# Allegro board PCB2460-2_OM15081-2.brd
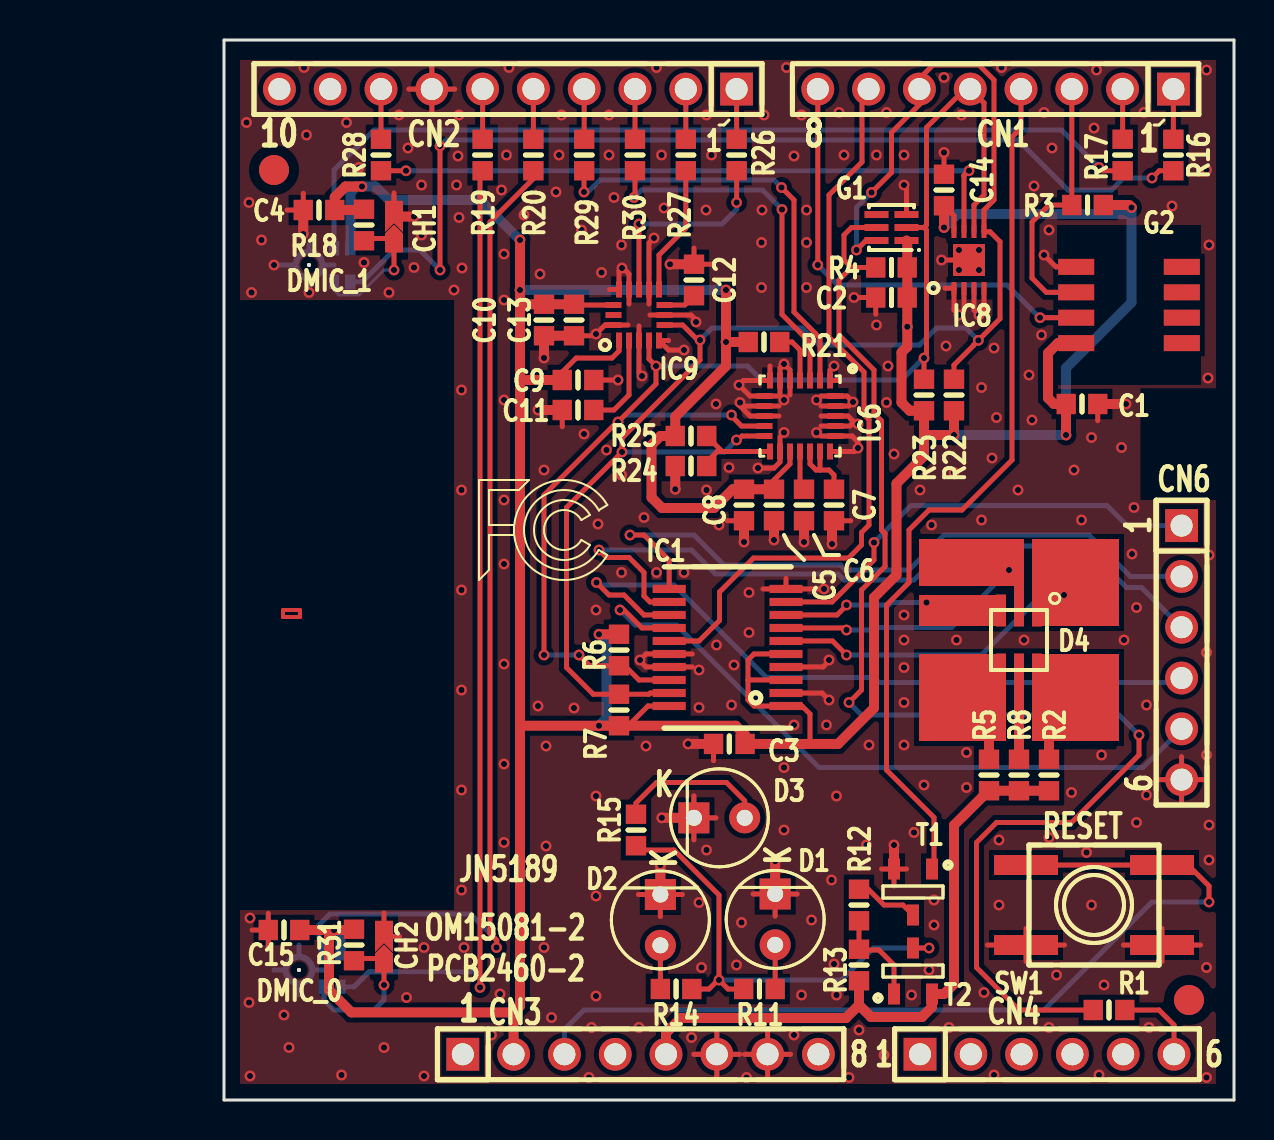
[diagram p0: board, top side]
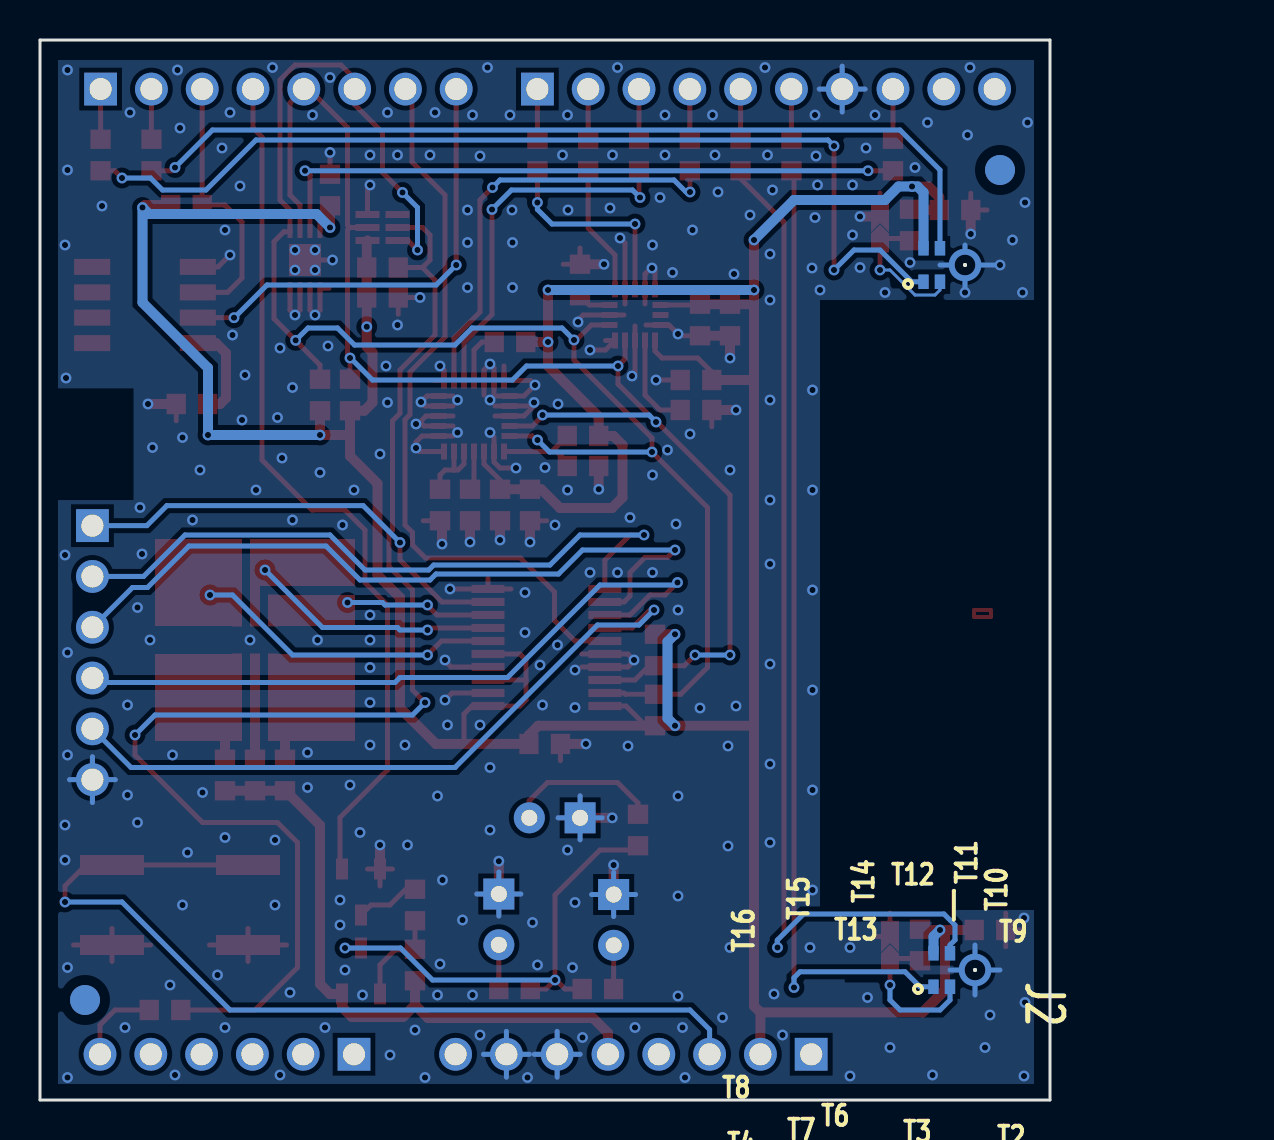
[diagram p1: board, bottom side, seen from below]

Outline 50.5 x 53 mm; copper layers: TOP, BOTTOM. Coordinates in mm from the lower left corner of the outline.
Outline path: 0,53 50.5,53 50.5,0 0,0 0,53

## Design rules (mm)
net group ALIM: nets VCC VCC3.3V VCC5V VIN
net group DEFAUT: nets I2C0_SCL I2C0_SDA N03174 N03180 N03190 N03428 N03542 N03710 N05589 N05601 N05625 N05637 N05653 N05814 N05832 N05850 N06055 N06079 N06104 N25754 N28193 N29430 N29717 N31644 N33464 N60487 N60495 N61570 N62140 N62201 N66287 N66291 N66417 N66481 N66485 N77953 N85458 PDM0_CLK PDM0_DATA PDM1_CLK PDM1_DATA PIO_2 PIO_3 PIO_4 PIO_7 PIO_15 PIO_16 PIO_18 PIO_19 PIO_21 PWM6 RSTN

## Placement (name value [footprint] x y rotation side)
1  BUBBLE-01  [BUBBLE_DIAM8]  -9.2 43.05 0 top
C1  100nF  [C0603]  42.9 34.8 0 top
C2  100nF  [C0603]  33.38 40.12 180 top
C3  100nF  [C0603]  25.27 17.8 180 top
C4  100nF  [C0603]  4.75 44.5 180 top
C5  100nF  [C0603]  27.5 29.75 270 top
C6  100nF  [C0603]  29 29.75 270 top
C7  100nF  [C0603]  30.5 29.75 90 top
C8  1uF  [C0603]  26 29.75 270 top
C9  100nF  [C0603]  17.7 36 180 top
C10  4.7uF  [C0603]  16 39 270 top
C11  100nF  [C0603]  17.7 34.5 0 top
C12  100nF  [C0603]  23.5 41 270 top
C13  100nF  [C0603]  17.5 39 90 top
C14  100nF  [C0603]  36 45.5 270 top
C15  100nF  [C0603]  3 8.5 180 top
CH1  NC  [CHEVRON_0603_O]  8.5 43.75 90 top
CH2  NC  [CHEVRON_0603_O]  8 7.75 90 top
CN1  -  [ESQ-108-14-L-S]  47.47 50.55 0 top
CN2  -  [ESQ-110-14-L-S]  25.63 50.55 0 top
CN3  -  [ESQ-108-14-L-S]  11.94 2.29 180 top
CN4  -  [ESQ-106-14-L-S]  34.8 2.29 180 top
CN6  -  [ESQ-106-14-L-S]  47.88 28.72 90 top
D1  WHITE  [LED_D5_A_K]  27.56 9.03 270 top
D2  WHITE  [LED_D5_A_K]  21.82 9 270 top
D3  WHITE  [LED_D5_A_K]  24.77 14.11 0 top
D4  B/G/R  [LED_PLCC6]  39.75 23 270 top
G1  TSL25721FN  [DFN6_065_2X2]  33.38 43.62 180 top
G2  SHT11_NC  [SENSOR_SHT11]  45.25 39.75 0 top
IC1  PCA9634  [TSSOP20_175_065]  25.18 22.63 180 top
IC4  -  [SPH0641LM4H-1]  4.25 41.75 90 bottom
IC5  -  [SPH0641LM4H-1]  3.75 6.5 90 bottom
IC6  FXAS21002C  [QFN24_050_4X4]  28.8 34.2 270 top
IC8  SE98ATP  [SOT1069-2_HWSON8]  37.25 42 0 top
IC9  FXOS8700CQR1  [QFN16_050_SQ3_NOPAD]  20.75 39.25 90 top
NOREF  -  []  315.6 -90.1 0 top
NOREF#2  -  [unnamed#2]  2.5 46.5 0 top
NOREF#3  -  []  16 0 90 top
NOREF#4  -  []  2.77 50.55 90 top
NOREF#5  -  []  13.7 -115.75 0 top
NOREF#6  -  []  -76.6 -194.1 0 top
NOREF#7  -  []  62.65 28.15 0 top
NOREF#8  -  []  0 0 90 top
NOREF#9  -  []  0 53 0 top
NOREF#10  -  []  0 53 0 top
NOREF#11  -  [unnamed#2]  48.25 5 0 top
NOREF#12  -  []  49.25 30.25 90 top
NOREF#13  -  []  299.4 3.2 0 top
NOREF#14  -  [unnamed#2]  48.25 5 180 bottom
NOREF#15  -  [unnamed#2]  2.5 46.5 180 bottom
R1  0R  [R0603]  44.25 4.5 0 top
R2  100R  [R0603]  41.25 16.25 90 top
R3  10K0  [R0603]  43.18 44.75 0 top
R4  10K0  [R0603]  33.38 41.62 180 top
R5  200R  [R0603]  38.25 16.25 90 top
R6  10K0  [R0603]  19.75 22.5 270 top
R7  10K0  [R0603]  19.75 19.5 90 top
R8  100R  [R0603]  39.75 16.25 90 top
R11  100R  [R0603]  26.77 5.55 0 top
R12  1K  [R0603]  31.75 9.75 270 top
R13  1K  [R0603]  31.75 6.75 270 top
R14  100R  [R0603]  22.61 5.55 180 top
R15  100R  [R0603]  20.6 13.5 90 top
R16  0R  [R0603]  47.47 47.25 90 top
R17  0R  [R0603]  44.93 47.25 90 top
R18  100K  [R0603]  7 43.75 270 top
R19  0R  [R0603]  12.93 47.25 90 top
R20  0R  [R0603]  15.47 47.25 90 top
R21  47K0  [R0603]  27 37.9 0 top
R22  4K70  [R0603]  36.5 35.25 90 top
R23  4K70  [R0603]  35 35.25 90 top
R24  NC  [R0603]  23.35 31.7 180 top
R25  47K0  [R0603]  23.35 33.2 180 top
R26  0R  [R0603]  25.63 47.25 90 top
R27  0R  [R0603]  23.09 47.25 90 top
R28  0R  [R0603]  7.85 47.25 90 top
R29  0R  [R0603]  18.01 47.25 270 top
R30  0R  [R0603]  20.55 47.25 270 top
R31  100K  [R0603]  6.5 7.75 270 top
SW1  EVQ-Q2P03W  [BP_EVQQ2]  43.5 9.75 0 top
T1  MMUN2211LT1G  [SOT23]  34.45 10.4 180 top
T2  BCV26  [SOT23]  34.45 6.45 0 top

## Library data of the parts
1 = BUBBLE: alternate symbols: (BUBBLE_DIAM4)
C1-C15 = CAPA: Tolerance: 10%; User Part Number: PARTNUM; alternate symbols: (0603C); tolerance: 10%
CH1 CH2 = CHEVRON_0603_OPEN
CN1 CN3 = HEADER_8P: Tolerance: TOL; User Part Number: PAR
CN2 = HEADER_10P: Tolerance: TOL; User Part Number: PAR
CN4 CN6 = HEADER_6P: Tolerance: TOL; User Part Number: PAR
D1-D3 = LED: User Part Number: PAR; Tolerance: TOL
D4 = LED_3_PLCC6: Tolerance: t; User Part Number: p
G1 = sensor_tsl2572_fn-6
G2 = SENSOR_SHT11: User Part Number: PARTNUM; Tolerance: TOLERANCE
IC1 = PCA9634_TSSOP20
IC4 IC5 = SPH0641LM4H-1: User Part Number: PARTNUM; Tolerance: TOLERANCE
IC6 = FXAS21002C
IC8 = SE98ATP: Tolerance: TOL; User Part Number: PN
IC9 = FXOS8700CQR1: User Part Number: BCNNUMBER; Tolerance: TOLERANCE
R1 R2 R5 R8 R11-R20 R26-R31 = RES: User Part Number: PARTNUM; Tolerance: 1%; alternate symbols: (0603R); tolerance: 1%
R3 R4 R6 R7 = RES: User Part Number: PARTNUM; Tolerance: 1%; tolerance: 1%
R21-R23 R25 = RES: User Part Number: PARTNUM; Tolerance: 5%; tolerance: 5%
R24 = RES: User Part Number: PARTNUM; Tolerance: -; tolerance: -
SW1 = BP_EVQQ2: User Part Number: PARTNUM; Tolerance: TOLERANCE
T1 = NPN_B1_E2_C3: User Part Number: PARTNUM; Tolerance: TOLERANCE
T2 = PNP_B1_E2_C3: User Part Number: PARTNUM; Tolerance: TOLERANCE

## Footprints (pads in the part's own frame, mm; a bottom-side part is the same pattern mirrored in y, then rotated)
BP_EVQQ2
  rect 3.2x1 smd: A(-3.4,-2) AP(3.4,-2) B(-3.4,2) BP(3.4,2)
BUBBLE_DIAM8
  round 0 smd: 1(0,0)
C0603
  rect 0.965x1.016 smd: 1(-0.787,0) 2(0.787,0)
CHEVRON_0603_O
  custom 0.225x0.225 smd: 1(-0.675,0) 2(0.425,0)
DFN6_065_2X2
  rect 1.2x0.35 smd: 1(-0.75,0.65) 2(-0.75,0) 3(-0.75,-0.65) 4(0.75,-0.65) 5(0.75,0) 6(0.75,0.65)
ESQ-106-14-L-S
  rect 1.64x1.64 hole 1.1: 1(0,0)
  round 1.64 hole 1.1: 2(-2.54,0) 3(-5.08,0) 4(-7.62,0) 5(-10.16,0) 6(-12.7,0)
ESQ-108-14-L-S
  rect 1.64x1.64 hole 1.1: 1(0,0)
  round 1.64 hole 1.1: 2(-2.54,0) 3(-5.08,0) 4(-7.62,0) 5(-10.16,0) 6(-12.7,0) 7(-15.24,0) 8(-17.78,0)
ESQ-110-14-L-S
  rect 1.64x1.64 hole 1.1: 1(0,0)
  round 1.64 hole 1.1: 2(-2.54,0) 3(-5.08,0) 4(-7.62,0) 5(-10.16,0) 6(-12.7,0) 7(-15.24,0) 8(-17.78,0) 9(-20.32,0) 10(-22.86,0)
LED_D5_A_K
  round 1.55 hole 0.8: A(1.27,0)
  rect 1.55x1.55 hole 0.8: K(-1.27,0)
LED_PLCC6
  rect 1.6x0.5 smd: 1(-1.475,0.9) 2(-1.475,0) 3(-1.475,-0.9) 4(1.475,-0.9) 5(1.475,0) 6(1.475,0.9)
QFN16_050_SQ3_NOPAD
  rect 0.8x0.3 smd: 1(-1.275,1) 2(-1.275,0.5) 3(-1.275,0) 4(-1.275,-0.5) 5(-1.275,-1) 9(1.275,-1) 10(1.275,-0.5) 11(1.275,0) 12(1.275,0.5) 13(1.275,1)
  rect 0.3x0.8 smd: 6(-0.5,-1.275) 7(0,-1.275) 8(0.5,-1.275) 14(0.5,1.275) 15(0,1.275) 16(-0.5,1.275)
QFN24_050_4X4
  rect 0.8x0.3 smd: 1(-1.775,1.5) 2(-1.775,1) 3(-1.775,0.5) 4(-1.775,0) 5(-1.775,-0.5) 6(-1.775,-1) 7(-1.775,-1.5) 13(1.775,-1.5) 14(1.775,-1) 15(1.775,-0.5) 16(1.775,0) 17(1.775,0.5) 18(1.775,1) 19(1.775,1.5)
  rect 0.3x0.8 smd: 8(-1,-1.775) 9(-0.5,-1.775) 10(0,-1.775) 11(0.5,-1.775) 12(1,-1.775) 20(1,1.775) 21(0.5,1.775) 22(0,1.775) 23(-0.5,1.775) 24(-1,1.775)
R0603
  rect 0.965x1.016 smd: 1(-0.787,0) 2(0.787,0)
SENSOR_SHT11
  rect 1.8x0.8 smd: 1(-2.64,1.905) 2(-2.64,0.635) 3(-2.64,-0.635) 4(-2.64,-1.905) 5(2.64,-1.905) 6(2.64,-0.635) 7(2.64,0.635) 8(2.64,1.905)
SOT23
  rect 0.6x1.05 smd: 1(-0.95,-1.15) 2(0.95,-1.15) 3(0,1.15)
SOT1069-2_HWSON8
  rect 0.25x0.625 smd: 1(-0.75,-1.413) 2(-0.25,-1.413) 3(0.25,-1.413) 4(0.75,-1.413) 5(0.75,1.413) 6(0.25,1.413) 7(-0.25,1.413) 8(-0.75,1.413)
  rect 1.6x1.6 smd: 9(0,0)
SPH0641LM4H-1
  round 0.2 hole 0.35 unplated: (0,0)
  rect 0.725x0.522 smd: 1(-0.838,2.074) 2(-0.838,1.252) 4(0.838,1.252) 5(0.838,2.074)
  round 0.25 smd: 3(0,-0.675)
TSSOP20_175_065
  rect 1.651x0.406 smd: 1(-2.921,2.926) 2(-2.921,2.276) 3(-2.921,1.626) 4(-2.921,0.975) 5(-2.921,0.325) 6(-2.921,-0.325) 7(-2.921,-0.975) 8(-2.921,-1.626) 9(-2.921,-2.276) 10(-2.921,-2.926) 11(2.921,-2.926) 12(2.921,-2.276) 13(2.921,-1.626) 14(2.921,-0.975) 15(2.921,-0.325) 16(2.921,0.325) 17(2.921,0.975) 18(2.921,1.626) 19(2.921,2.276) 20(2.921,2.926)
unnamed#2
  round 1.5 smd: (0,0)

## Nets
GND: C1.2 C2.2 C3.2 C4.2 C5.2 C6.2 C7.1 C8.2 C9.1 C10.2 C11.1 C12.1 C13.1 C14.1 C15.2 CH1.2 CH2.2 CN2.7 CN3.6 CN3.7 CN6.6 D1.K D2.K D3.K G1.3(GND) G2.1(GND) IC1.2(A1) IC1.4(A3) IC1.10(GND) IC1.16(A5) IC1.17(A6) IC4.3(GND) IC5.3(GND) IC6.1(GND1) IC6.5(GND2) IC6.6(RSVD) IC6.7(RSVD2) IC6.8(I2C/SPI) IC6.9(RSVD/GND) IC6.10(RSVD/GND2) IC6.14(GND3) IC6.19(GND4) IC6.20(RSVD3) IC6.21(RSVD4) IC6.22(RSVD5) IC6.23(RSVD6) IC6.24(RSVD7) IC8.1(A0) IC8.2(A1) IC8.3(A2) IC8.4(VSS) IC8.9(PAD) IC9.3(RESERVED) IC9.5(GND) IC9.7(SA0/MISO) IC9.10(SA1/CS_B) IC9.12(GND2) IC9.13(RESERVED2) IC9.16(RST) R24.2 SW1.A SW1.AP T1.2(E)
VCC: C1.1 C2.1 C3.1 C4.1 C5.1 C8.1 C9.2 C10.1 C13.2 C14.2 C15.1 CN3.2 G1.1(VDD) G2.4(VDD) IC1.1(AO) IC1.3(A2) IC1.5(A4) IC1.20(VCC) IC4.5(VDD) IC5.5(VDD) IC6.15(VDD) IC8.8(VDD) IC9.1(VDDIO) IC9.14(VDD) R3.2 R4.1 R6.1 R7.1 R18.1 R21.1 R22.1 R23.1 R25.2 R31.1
VCC3.3V: CN3.4
VCC5V: CN3.5 R2.1 R5.1 R8.1 R13.2 T2.2(E)
VIN: CN3.8
I2C0_SCL: CN1.5 G1.2(SCL) IC1.18(SCL) IC6.11(SCL/SCLK) IC8.6(SCL) IC9.4(SCL/SCLK) R6.2 R23.2
I2C0_SDA: CN1.6 G1.6(SDA) IC1.19(SDA) IC6.12(SDA/MOSI) IC8.5(SDA) IC9.6(SDA/MOSI) R7.2 R22.2
PDM0_CLK: CN2.5 R20.2
PDM0_DATA: CN2.6 R19.2
PDM1_CLK: CN1.2 R17.2
PDM1_DATA: CN1.1 R16.2
PIO_2: CN2.4 R29.1
PIO_3: CN2.2 R27.2
PIO_4: CN2.3 R30.1
PIO_7: CN1.8 G2.3(SCK)
PIO_15: CN1.3 G2.2(DATA) R3.1
PIO_16: CN1.7 IC1.15(OE)
PIO_18: CN2.1 R26.2
PIO_19: CN2.8 R28.2
PIO_21: CN4.6 R1.2
PWM6: CN1.4 T1.1(B)
RSTN: CN3.3 SW1.B SW1.BP
N03174: D1.A R11.2
N03180: D2.A R14.2
N03190: D3.A R15.2
N03428: R11.1 R14.1 R15.1 T2.3(C)
N03542: R12.2 R13.1 T2.1(B)
N03710: R12.1 T1.3(C)
N05589: CN6.5 IC1.14(L7)
N05601: CN6.4 IC1.13(L6)
N05625: CN6.3 IC1.12(L5)
N05637: CN6.2 IC1.11(L4)
N05653: CN6.1 IC1.9(L3)
N05814: D4.3(K3) IC1.8(L2)
N05832: D4.2(K2) IC1.7(L1)
N05850: D4.1(K1) IC1.6(L0)
N06055: D4.6(A6) R2.2
N06079: D4.5(A5) R8.2
N06104: D4.4(A4) R5.2
N25754: IC6.4(RST_B) R21.2
N28193: IC6.13(SA0/MISO) R24.1 R25.1
N29430: C6.1 IC6.16(VREGD)
N29717: C7.2 IC6.17(SPI_CS_B) IC6.18(VDDIO)
N31644: C11.2 IC9.2(BYP)
N33464: C12.2 IC9.8(CRST)
N60487: IC9.11(INT1) R26.1
N60495: IC9.9(INT2) R27.1
N61570: IC8.7(EVENT) R28.1
N62140: IC6.2(INT2) R29.2
N62201: IC6.3(INT1) R30.2
N66287: IC4.1(DATA) R16.1
N66291: IC4.4(CLK) R17.1
N66417: CH1.1 IC4.2(SELECT) R18.2
N66481: IC5.1(DATA) R19.1
N66485: IC5.4(CLK) R20.1
N77953: CH2.1 IC5.2(SELECT) R31.2
N85458: G1.5(INT) R1.1 R4.2

Pads without a net: 1 1; CN2 9 10; CN3 1; CN4 1 2 3 4 5; G1 4; G2 5 6 7 8; IC9 15

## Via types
v1: diameter 0.54, hole 0.31, TOP to BOTTOM, 331 vias

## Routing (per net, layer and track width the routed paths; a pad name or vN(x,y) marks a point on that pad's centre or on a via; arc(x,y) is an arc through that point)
GND: length 184.4
  TOP w0.25: v1(30.5,36.7) 30.3,36.5 IC6.1 30.78,35.98 ; v1(30.25,22) 30.25,21.95 29.95,21.65 IC1.4 ; 9.24,50.55 CN2.7 ; CN2.7 10.39,49.4 ; CN2.7 11.54,50.55 ; CN2.7 10.39,51.69 ; SW1.A 40.1,8.58 ; SW1.A 38.17,7.75 ; SW1.A 40.1,6.92 ; SW1.A 42.03,7.75 ; 27.3,36.7 IC6.7 25.98,35.98 v1(25.75,35.75) 26.3,35.2 27.75,35.2 ; CN3.7 27.18,3.43 ; CN3.7 28.33,2.29 ; CN3.7 27.18,1.14 ; CN3.7 26.03,2.29 ; 46.9,6.92 SW1.AP ; SW1.AP 48.83,7.75 ; SW1.AP 44.97,7.75 ; SW1.AP 46.9,8.58 ; 20.2,38.75 IC9.16 19.05,38.75 v1(18.6,38.3) ; 33.5,10.7 T1.2 ; T1.2 34.13,11.55 ; T1.2 32.87,11.55 ; 24.64,1.14 CN3.6 ; CN3.6 24.64,3.43 ; CN3.6 25.79,2.29 ; CN3.6 23.49,2.29 ; 24.33,41.79 C12.1 23.5,42.6 ; 30.3,32.42 31.52,32.42 v1(31.7,32.6) 31.7,32.9 31.4,33.2 IC6.20 29.85,33.2 ; CN6.6 47.88,17.16 ; CN6.6 46.73,16.02 ; CN6.6 47.88,14.87 ; CN6.6 49.02,16.02 ; IC8.2 37,39.5 v1(36.75,39.25) 36.5,39.5 IC8.1 36.05,40.59 ; 21.25,39.8 IC9.10 21.25,42.85 v1(21.5,43.1) ; 23.41,21.65 IC1.17 21.1,21.65 20.8,21.95 v1(20.8,22) 21.1,22.3 IC1.16 23.41,22.3 ; 25.17,28.96 C8.2 ; 24.48,16.97 C3.2 ; 2.21,7.67 C15.2 ; C15.2 1.4,8.5 ; C15.2 2.21,9.33 ; G2.1 41.59,41.66 v1(41,42.25) ; 29.85,33.7 IC6.21 31.3,33.7 31.4,33.8 31.6,33.8 ; 27.56,9.2 D1.K ; D1.K 26.46,10.3 ; D1.K 28.66,10.3 ; D3.K 24.6,14.11 ; D3.K 23.5,15.21 ; D3.K 23.5,13.01 ; v1(34,45.75) 34.12,45.62 G1.3 ; IC1.2 29.9,20.35 v1(30.25,20) ; 28.3,35.25 IC6.5 28.3,36.5 v1(28,36.8) 27.8,36.6 IC6.6 27.8,35.25 ; 21.82,9.17 D2.K ; D2.K 20.72,10.27 ; D2.K 22.92,10.27 ; C13.1 18.33,38.21 ; 27.75,34.2 26.3,34.2 25.8,34.7 ; IC8.3 37.5,39.5 v1(37.75,39.25) 38,39.5 IC8.4 ; 30.5,28.15 C7.1 31.33,28.96 ; IC1.10 28.1,26.08 ; IC1.10 v1(30,25.55) ; IC1.10 26.95,25.55 ; 16.91,33.67 C11.1 ; 32.59,39.29 C2.2 31.78,40.12 ; 21.3,39.25 IC9.7 23.35,39.25 23.6,39 v1(23.6,38.9) ; 29.85,34.7 IC6.23 31.25,34.7 v1(31.45,34.9) 31.15,35.2 IC6.24 29.85,35.2 ; 25.8,34.7 v1(25.8,34.88) ; 25.8,34.7 27.75,34.7 ; 8,9.35 CH2.2 8.78,8.18 ; 3.15,44.5 C4.2 3.96,45.33 ; 29.85,34.2 IC6.22 31.2,34.2 31.6,33.8 ; 27.8,33.15 27.8,31.9 27.5,31.6 v1(26.7,31.6) ; 22.23,37.98 IC9.5 22.23,37.5 v1(23,37.5) ; 31.6,33.8 v1(31.7,33.8) ; C9.1 v1(19.7,36) ; C14.1 v1(36,47.38) ; CH1.2 8.5,45.35 ; 36.12,42 IC8.9 ; 20.75,38.7 IC9.3 20.75,36.35 v1(20.9,36.2) ; 43.69,33.97 C1.2 ; 20.25,39.8 IC9.12 20.25,41.3 19.95,41.6 v1(19.9,41.6) 19.75,41.45 IC9.13 19.27,40.52
  TOP w0.5: CH1.2 v1(9.5,44.17) ; T1.2 v1(33.5,12.75) ; C8.2 v1(26,27.9) ; C13.1 C10.2 v1(16,37.1) ; D2.K v1(21.82,11.75) ; C6.2 v1(29,27.9) ; C3.2 v1(23.2,17.8) ; D3.K v1(21.89,14.11) ; C5.2 v1(27.5,28) ; C12.1 v1(22.3,41.79) ; C1.2 v1(45.1,34.8) ; D1.K v1(27.56,11.94) ; C11.1 v1(15.7,34.5) ; R24.2 v1(22.56,30.54) ; C7.1 30.4,28.86 v1(30.4,27.8) ; v1(3.96,43.3) C4.2
  BOTTOM w0.25: 26.46,10.3 D1.K ; D1.K 28.66,10.3 ; D1.K 27.56,9.2 ; D1.K 27.56,11.4 ; 4.25,41 v1(4.25,40.38) ; CN3.7 28.33,2.29 ; CN3.7 26.03,2.29 ; CN3.7 27.18,1.14 ; CN3.7 27.18,3.43 ; 4.25,42.5 4.25,42.75 ; 10.39,49.4 CN2.7 ; CN2.7 10.39,51.69 ; CN2.7 9.24,50.55 ; CN2.7 11.54,50.55 ; CN6.6 47.88,17.16 ; CN6.6 46.73,16.02 ; CN6.6 49.02,16.02 ; CN6.6 47.88,14.87 ; D3.K 23.5,15.21 ; D3.K 23.5,13.01 ; D3.K 22.39,14.11 ; D3.K 24.6,14.11 ; IC5.3 2.5,6.5 ; 23.49,2.29 CN3.6 ; CN3.6 25.79,2.29 ; CN3.6 24.64,1.14 ; CN3.6 24.64,3.43 ; 20.72,10.27 D2.K ; D2.K 21.82,9.17 ; D2.K 21.82,11.37 ; D2.K 22.92,10.27 ; IC4.3 v1(2.5,41.75) ; 5.5,41.75 5,41.75 ; 5,6.5 4.5,6.5 ; 3.75,5.25 3.75,5.75 ; 3.75,7.75 3.75,7.25
  vias: v1(1.12,48.88) v1(1.25,44.88) v1(1.25,4.88) v1(1.3,9.1) v1(1.3,1.2) v1(1.38,40.38) v1(1.88,43) v1(3,4.25) v1(3.25,2.62) v1(4,51.62) v1(4.12,48.25) v1(5.88,1.25) v1(6.12,48.88) v1(6.75,46.62) v1(7,41.88) v1(8,2.62) v1(8.25,40.38) v1(8.75,49.25) v1(9.12,5.12) v1(9.2,47.6) v1(9.5,41.62) v1(9.88,45.75) v1(9.88,43.25) v1(10,7.62) v1(10,1.2) v1(11.5,40.5) v1(11.62,45.75) v1(11.7,47.2) v1(11.75,49.25) v1(11.75,44.12) v1(11.9,41.6) v1(11.88,35.5) v1(11.88,30.5) v1(11.88,25.5) v1(11.88,20.5) v1(11.88,15.5) v1(11.88,10.5) v1(12,7.62) v1(13.38,3.25) v1(13.8,5.3) v1(13.88,45.5) v1(14,42.3) v1(14,40) v1(14,35) v1(14,30) v1(14,26.8) v1(14,21.8) v1(14,16.8) v1(14,12.88) v1(14.12,47.25) v1(14.25,51.62) v1(15,44.25) v1(15.7,19.7) v1(15.8,41.3) v1(16,31.5) v1(16,7.62) v1(16.1,17.7) v1(16.1,12.7) v1(16.38,4.12) v1(16.6,45.4) v1(16.75,47.25) v1(16.88,49.25) v1(17.5,19.6) v1(17.88,43.5) v1(18,33.3) v1(18.25,1.12) v1(18.38,3.62) v1(18.6,24.5) v1(18.6,15.2) v1(18.6,10.2) v1(18.6,5.2) v1(18.7,28.8) v1(18.88,41.38) v1(19.12,32.5) v1(19.25,49.25) v1(19.25,47.25) v1(19.5,45.12) v1(19.88,42.75) v1(19.88,31.25) v1(19.88,26.38) v1(20.75,3.62) v1(21,29.12) v1(21.1,17.7) v1(21.62,51.62) v1(21.62,26.38) v1(21.88,47.25) v1(22,44.6) v1(23,26.38) v1(23.38,3.12) v1(23.75,21.5) v1(23.75,19.62) v1(23.75,9.88) v1(23.88,6.62) v1(24.12,49.25) v1(24.1,44.5) v1(24.12,30.5) v1(24.12,12.5) v1(24.38,47.25) v1(24.6,34.8) v1(24.62,22.75) v1(24.75,28.75) v1(25.25,31.62) v1(25.38,19.75) v1(25.5,21.75) v1(25.62,6.75) v1(25.88,8.88) v1(26.12,1.12) v1(26.25,25.38) v1(26.25,23.38) v1(26.9,44.5) v1(26.88,42.88) v1(26.88,40.62) v1(27,49.25) v1(28,35) v1(28,33.38) v1(28,16.62) v1(28,13.5) v1(28.12,51.62) v1(28.5,47.2) v1(28.5,18.75) v1(28.5,3.25) v1(28.88,49.25) v1(28.88,5.25) v1(29.12,44.5) v1(29.12,42.88) v1(29.12,40.62) v1(29.38,9) v1(29.62,35) v1(29.62,33.38) v1(30.12,18.75) v1(30.38,11) v1(30.5,6.8) v1(30.62,15.2) v1(30.62,5.25) v1(30.75,49.38) v1(31,47.25) v1(31.25,1.12) v1(31.5,40.12) v1(31.75,3.5) v1(32.12,12.75) v1(32.25,17.75) v1(32.62,47.25) v1(32.62,38.75) v1(33,2.25) v1(33.12,49.38) v1(33.12,34.88) v1(33.2,36.7) v1(33.5,32.3) v1(34,47.25) v1(34,24.25) v1(34,23) v1(34,21.62) v1(34,19.88) v1(34,17.75) v1(34.38,5.25) v1(34.5,13.38) v1(34.8,30.5) v1(35,15.75) v1(35.25,6.5) v1(35.38,28.75) v1(35.5,10) v1(35.5,8.75) v1(35.88,42) v1(36,51.12) v1(36.1,37.7) v1(36.25,3.62) v1(36.5,31.38) v1(36.62,23) v1(36.75,42.5) v1(36.75,41.5) v1(36.88,49.25) v1(37.12,17.38) v1(37.12,15.62) v1(37.75,42.5) v1(37.75,41.5) v1(37.88,35.62) v1(37.88,29) v1(38,5.38) v1(38.4,32.1) v1(38.5,37.6) v1(38.5,1.25) v1(38.62,34.12) v1(38.75,13) v1(38.75,9.75) v1(38.88,51.62) v1(39.7,30.5) v1(40,23) v1(40.25,36.25) v1(40.4,34) v1(40.5,45.7) v1(40.88,38.25) v1(41,49.38) v1(41.25,43.5) v1(41.25,13.12) v1(41.25,3.62) v1(41.4,47.6) v1(41.62,6.25) v1(42.38,15.38) v1(42.5,31.5) v1(42.88,29) v1(43.12,12.38) v1(43.38,33.12) v1(43.38,9.75) v1(43.5,48.6) v1(43.62,51.5) v1(43.75,1.25) v1(43.88,17.25) v1(44,5.75) v1(44.88,32.62) v1(45,23) v1(45.4,27.3) v1(45.5,29.62) v1(45.62,24.62) v1(45.62,13.88) v1(46,49.38) v1(46.12,19.75) v1(46.12,15.25) v1(46.25,3.62) v1(47.4,44.7) v1(49.12,51.5) v1(49.12,46.5) v1(49.12,22.38) v1(49.12,17.25) v1(49.12,6.62) v1(49.12,1.12) v1(49.25,42.75) v1(49.2,36.1) v1(49.25,27.25) v1(49.25,13.75) v1(49.25,12)
VCC: length 222.7
  TOP w0.25: IC1.5 26.5,22.3 26.2,22 26.2,21 ; 28.3,32.42 28.3,31.8 27.5,31 C5.1 ; IC9.14 17.54,39.75 C13.2 ; IC9.1 19.75,37.45 19.4,37.1 17.61,37.1 16.91,36.4 C9.2 ; C14.2 36.5,44.21 IC8.8 ; 26.2,21 IC1.3 ; 26.2,21 26.2,20 26.5,19.7 IC1.1 28.9,19.7 29.3,19.3 29.3,17.9 29.2,17.8 ; IC1.20 21.2,19.7 20.21,18.71
  TOP w0.5: 14.48,4.38 14.8,4.7 14.8,18.75 ; 14.48,4.38 CN3.2 ; 14.48,4.38 6.37,4.38 5.25,5.5 5.25,8.25 v1(5.5,8.5) ; v1(6.9,45.68) 6.08,45.68 5.54,45.14 C4.1 6.96,44.5 R18.1 ; 14.8,18.75 14.84,18.71 v1(18.75,18.71) R7.1 25.59,18.71 26.05,18.25 C3.1 30.7,17.8 32.5,19.6 32.5,25.12 33.62,26.25 33.62,30.82 35,32.2 35,33.2 ; 14.8,18.75 14.8,36 ; 14.8,36 14.8,39.79 ; 14.8,36 C9.2 ; v1(45.38,44.62) 45.25,44.75 R3.2 ; R31.1 6.46,8.5 v1(5.5,8.5) ; R6.1 v1(18.75,23.29) ; 14.8,39.79 v1(14.8,40.5) v1(14.8,43) ; 14.8,39.79 C10.1 C13.2 ; 35,33.2 R23.1 34.29,34.46 33.88,34.88 33.88,37.38 34.16,37.66 v1(34.16,38.66) C2.1 R4.1 34.16,42.94 G1.1 ; 35,33.2 35.05,33.25 v1(36.5,33.25) R22.1 ; v1(42.1,33.25) 42.1,34.79 C1.1 41.5,34.8 41.2,35.1 41.2,37.34 41.7,37.84 G2.4 ; C5.1 C8.1 25.44,30.54 24.5,29.6 21.9,29.6 21.38,30.12 21.38,32.75 21.82,33.2 R25.2 22.56,34.16 25.1,36.7 v1(25.1,37.9) ; v1(5.5,8.5) C15.1 ; v1(25.1,37.9) R21.1 ; v1(25.1,37.9) v1(25.1,40.5) ; C14.2 v1(36,43.62)
  BOTTOM w0.5: v1(18.75,18.71) 19.12,19.09 19.12,22.91 v1(18.75,23.29) ; v1(36,43.62) 36.67,44.3 45.05,44.3 v1(45.38,44.62) 45.38,39.88 42.1,36.6 v1(42.1,33.25) v1(36.5,33.25) ; v1(14.8,43) 12.8,45 8.25,45 7.57,45.68 v1(6.9,45.68) 6.62,45.68 6.32,45.38 IC4.5 ; IC5.5 5.82,8.18 v1(5.5,8.5) ; v1(25.1,40.5) v1(14.8,40.5)
VCC5V: length 32
  TOP w0.5: R2.1 R8.1 R5.1 38.22,15.46 36.5,13.74 36.5,5.8 36,5.3 T2.2 35.4,4.65 34.9,4.15 32.35,4.15 31.75,4.75 ; 31.75,4.75 31.1,4.1 22.85,4.1 22.1,3.35 CN3.5 ; 31.75,4.75 R13.2
I2C0_SCL: length 71.1
  TOP w0.25: IC8.6 37.5,44.75 38,45.25 38,49.86 CN1.5 37.05,50.55 35.12,48.62 35.12,43.75 35,43.62 ; v1(16,22.25) 16,30.25 19.65,33.9 v1(19.7,33.9) 21.6,35.8 v1(21.6,36.7) 21.25,37.05 IC9.4 ; IC1.18 20.75,21 20.04,21.71 R6.2 18.29,21.71 v1(17.75,22.25) ; 35,43.62 35.12,43.5 35.12,37.23 v1(35,37.1) R23.2 ; 35,43.62 G1.2 ; 27.02,33.7 25.88,33.7 25.38,34.2 v1(25.38,34.25)
  BOTTOM w0.25: v1(19.7,33.9) 20.05,34.25 v1(25.38,34.25) ; v1(17.75,22.25) v1(16,22.25) ; v1(35,37.1) 34.98,37.1 33.88,36 26.88,36 26.18,36.7 v1(21.6,36.7)
I2C0_SDA: length 81.5
  TOP w0.25: G1.6 32.1,42.98 v1(31.62,42.5) ; IC1.19 21.31,20.35 21.25,20.29 R7.2 18.46,20.29 17.12,21.62 17.12,29.62 v1(19.9,32.4) 19.9,33.1 23.8,37 v1(23.8,38) 23.68,38 22.93,38.75 IC9.6 ; v1(32.38,45.38) 33.38,46.38 33.38,48.38 34.77,49.77 CN1.6 34.77,51.07 35.45,51.75 37.75,51.75 38.5,51 38.5,45 38,44.5 IC8.5 38.3,43.41 38.8,42.91 38.8,39.07 v1(37.72,37.98) 37.48,37.75 37.48,37.73 36.5,36.75 R22.2 ; 27.02,33.2 25.9,33.2 25.7,33 v1(25.62,33)
  BOTTOM w0.25: v1(25.62,33) 25.02,32.4 v1(19.9,32.4) ; v1(32.38,45.38) 31.62,44.62 v1(31.62,42.5) ; v1(37.72,37.98) 37.1,38.6 35.62,38.6 34.77,37.75 29.75,37.75 28.9,38.6 24.4,38.6 v1(23.8,38)
PDM0_CLK: length 2.5
  TOP w0.25: CN2.5 R20.2
PDM0_DATA: length 2.5
  TOP w0.25: CN2.6 R19.2
PDM1_CLK: length 2.5
  TOP w0.25: CN1.2 R17.2
PDM1_DATA: length 2.5
  TOP w0.25: CN1.1 R16.2
PIO_2: length 2.5
  TOP w0.25: CN2.4 R29.1
PIO_3: length 2.5
  TOP w0.25: CN2.2 R27.2
PIO_4: length 2.5
  TOP w0.25: CN2.3 R30.1
PIO_7: length 22.8
  TOP w0.25: v1(40.8,39.12) G2.3 ; v1(29.69,41.75) CN1.8
  BOTTOM w0.25: v1(29.69,41.75) 30.69,40.75 39.15,40.75 40.78,39.12 v1(40.8,39.12)
PIO_15: length 13.4
  TOP w0.25: CN1.3 R3.1 41.25,44.75 40.4,43.9 40.4,41.1 41.12,40.38 G2.2
PIO_16: length 37.1
  TOP w0.25: CN1.7 32.2,50.55 31.9,50.25 31.9,46.9 30.25,45.25 30.25,38.15 32,36.4 32,34.27 32.25,34.02 32.25,28.75 31.88,28.38 31.88,27.75 31.23,27.1 26.48,27.1 24.77,25.4 24.77,23.98 23.75,22.95 IC1.15
PIO_18: length 2.5
  TOP w0.25: CN2.1 R26.2
PIO_19: length 2.5
  TOP w0.25: CN2.8 R28.2
PIO_21: length 4.2
  TOP w0.25: CN4.6 47.5,3.75 46.75,4.5 R1.2
PWM6: length 43.8
  TOP w0.25: CN1.4 39.85,48.6 39.4,48.15 39.4,32 36.9,29.5 35.25,29.5 34.25,28.5 34.25,25.88 33.12,24.75 33.12,16.5 35.5,14.12 35.5,11.65 T1.1
RSTN: length 46.5
  TOP w0.25: SW1.B SW1.BP 48.2,11.75 49.25,10.7 v1(49.25,9.9)
  BOTTOM w0.25: v1(49.25,9.9) 46.4,9.9 41,4.5 18,4.5 17.02,3.52 CN3.3
N03174: length 2.2
  TOP w0.25: R11.2 D1.A
N03180: length 2.2
  TOP w0.25: R14.2 D2.A
N03190: length 7.7
  TOP w0.25: D3.A 26.04,14.96 25.12,15.88 21.62,15.88 20.6,14.85 R15.2
N03428: length 24.3
  TOP w0.25: R11.1 25.2,5.55 v1(24.75,6) ; v1(24.75,6) 24.7,6 24.25,5.55 R14.1 ; v1(24.75,6) 24.75,10.25 22.5,12.5 20.81,12.5 R15.1 ; T2.3 v1(35.25,7.6)
  BOTTOM w0.25: v1(24.75,6) 30.88,6 32.48,7.6 v1(35.25,7.6)
N03542: length 5
  TOP w0.25: R12.2 R13.1 31.79,7.5 32.75,7.5 33.5,6.75 T2.1
N03710: length 3.2
  TOP w0.25: R12.1 32.21,10.54 33,9.75 33.95,9.75 T1.3
N05589: length 35
  TOP w0.25: IC1.14 20.9,23.6 20,24.5 v1(19.8,24.5)
  BOTTOM w0.25: v1(19.8,24.5) 20.55,23.75 22.62,23.75 29.75,16.62 45.95,16.62 CN6.5
N05601: length 35.7
  TOP w0.25: v1(18.62,25.88) 19.25,25.25 20,25.25 21,24.25 IC1.13
  BOTTOM w0.25: v1(18.62,25.88) 18.75,25.75 22.5,25.75 27.12,21.12 32.5,21.12 32.75,20.88 47.66,20.88 CN6.4
N05625: length 37.4
  TOP w0.25: v1(18.75,27.5) 19.12,27.12 20.25,27.12 21,26.38 21,25.2 21.3,24.9 IC1.12
  BOTTOM w0.25: v1(18.75,27.5) 23.38,27.5 24.57,26.3 30.7,26.3 31,26 34.5,26 36.2,27.7 43.05,27.7 45.12,25.62 45.88,25.62 47.86,23.64 CN6.3
N05637: length 33.8
  TOP w0.25: IC1.11 22.26,26.99 21,28.25 v1(20.3,28.25)
  BOTTOM w0.25: CN6.2 45.32,26.18 43.25,28.25 36,28.25 34.25,26.5 31.07,26.5 30.82,26.75 25,26.75 23.5,28.25 v1(20.3,28.25)
N05653: length 22.7
  TOP w0.25: IC1.9 30.4,24.9 32.5,27 v1(32.5,27.88)
  BOTTOM w0.25: CN6.1 45.16,28.72 44.16,29.72 34.34,29.72 v1(32.5,27.88)
N05814: length 7.3
  TOP w0.25: IC1.8 30.65,24.25 31.12,24.73 v1(31.12,24.75)
  BOTTOM w0.25: v1(35.12,24.88) 33.38,24.88 33.25,24.75 v1(31.12,24.75)
N05832: length 12.4
  TOP w0.25: IC1.7 31.02,23.6 v1(31.12,23.5)
  BOTTOM w0.25: v1(31.12,23.5) 32.5,23.5 32.62,23.62 36.38,23.62 v1(39.25,26.5)
N05850: length 15.4
  TOP w0.25: v1(31.12,22.25) 30.42,22.95 IC1.6
  BOTTOM w0.25: v1(42,25.25) 40.88,25.25 37.88,22.25 v1(31.12,22.25)
N06055: length 1.2
  TOP w0.5: R2.2 41.25,18.25
N06079: length 1.2
  TOP w0.5: R8.2 39.75,18.25
N06104: length 1.2
  TOP w0.5: R5.2 38.25,18.25
N25754: length 2.7
  TOP w0.25: R21.2 28.4,37.9 28.8,37.5 IC6.4
N28193: length 4.7
  TOP w0.25: 24.91,32.42 R25.1 ; 24.91,32.42 24.66,32.42 24.14,31.9 R24.1 ; 24.91,32.42 27.3,32.42
N29430: length 2
  TOP w0.25: C6.1 28.8,30.74 28.8,32.42
N29717: length 3.7
  TOP w0.25: C7.2 30.5,31.25 30.25,31.5 29.8,31.5 ; 29.3,32.42 29.3,31.8 29.6,31.5 29.8,31.5 ; 29.8,31.5 29.8,32.42
N31644: length 4.8
  TOP w0.25: C11.2 19.5,34.5 20.25,35.25 IC9.2
N33464: length 1.7
  TOP w0.25: C12.2 23.04,39.75 IC9.8
N60487: length 10.4
  TOP w0.25: v1(25.63,44.88) R26.1 ; IC9.11 v1(20.75,43.8)
  BOTTOM w0.25: v1(25.63,44.88) 25.63,44.53 24.9,43.8 v1(20.75,43.8)
N60495: length 6.5
  TOP w0.25: R27.1 23.09,43.59 21.75,42.25 IC9.9
N61570: length 32.9
  TOP w0.25: 37,46.21 37,46.25 37.25,46.5 ; 37,46.21 IC8.7 ; 37,46.21 v1(37.25,46.46) ; R28.1 v1(9.1,46.46)
  BOTTOM w0.25: v1(37.25,46.46) v1(9.1,46.46)
N62140: length 21.8
  TOP w0.25: R29.2 18,46.45 v1(18,45.4) ; v1(27.88,45.62) 28.5,45 28.5,39.4 29.8,38.1 IC6.2
  BOTTOM w0.25: v1(27.88,45.62) 27.5,46 18.8,46 18.2,45.4 v1(18,45.4)
N62201: length 18.4
  TOP w0.25: IC6.3 29.3,37.88 27.9,39.27 v1(27.9,44.52) ; R30.2 20.55,45.17 v1(20.5,45.12)
  BOTTOM w0.25: v1(20.5,45.12) 20.88,45.5 26.93,45.5 v1(27.9,44.52)
N66287: length 50
  TOP w0.25: v1(46.4,46.1) 46.76,46.46 R16.1 ; v1(10.8,47.7) v1(10.8,41.5)
  BOTTOM w0.25: v1(46.4,46.1) 44.98,46.1 44.38,45.5 42.2,45.5 39.7,48 11.1,48 v1(10.8,47.7) ; IC4.1 6.91,40.91 8.5,42.5 9.8,42.5 v1(10.8,41.5)
N66291: length 45
  TOP w0.25: v1(43.75,46.62) 43.91,46.46 R17.1
  BOTTOM w0.25: IC4.4 5.5,46.5 7.5,48.5 41.88,48.5 v1(43.75,46.62)
N66417: length 7.2
  TOP w0.25: v1(8.5,41.5) CH1.1 7.11,43.08 R18.2
  BOTTOM w0.15: IC4.2 5.5,40.5 5.75,40.25 6.75,40.25 8,41.5 v1(8.5,41.5)
N66481: length 48.8
  TOP w0.25: R19.1 12.8,46.33 v1(12.8,5.62)
  BOTTOM w0.25: IC5.1 6.5,5.66 7.25,6.41 12.5,6.41 12.8,6.11 v1(12.8,5.62)
N66485: length 51.4
  TOP w0.25: R20.1 15.47,46.07 13.3,43.9 13.3,8.32 13.64,7.99 13.64,7.64 v1(13.62,7.62)
  BOTTOM w0.25: IC5.4 5,7.75 4.75,8 4.75,8.75 5.3,9.3 12.32,9.3 13.64,7.99 13.64,7.64 v1(13.62,7.62)
N77953: length 7.7
  TOP w0.25: R31.2 6.61,7.08 CH2.1 v1(8,5.75)
  BOTTOM w0.25: IC5.2 5,5.66 5,5 5.5,4.5 7.5,4.5 8,5 v1(8,5.75)
N85458: length 67.6
  TOP w0.25: R4.2 31.38,41.62 ; 31.38,41.62 31,42 31,43.25 31.38,43.62 G1.5 ; 31.38,41.62 30.75,41 30.75,38.25 32.5,36.5 32.5,34.34 32.88,33.96 32.88,28.5 33.05,28.32 33.05,26.68 31.88,25.5 31.88,20.5 v1(31.25,19.88) ; v1(45.75,18.25) 45.75,17.25 42.38,13.88 38.62,13.88 37.62,12.88 37.62,6.62 39.75,4.5 R1.1
  BOTTOM w0.25: v1(45.75,18.25) 44.75,19.25 31.88,19.25 v1(31.25,19.88)

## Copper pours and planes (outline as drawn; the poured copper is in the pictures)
GND on BOTTOM (solid shape): outline of 115 points within 3.44,40.93 5.07,42.56
GND on BOTTOM (solid shape): outline of 116 points within 2.93,5.68 4.56,7.32
GND on TOP: 0.8,0.8 0.8,9.5 11.5,9.5 11.5,40 0.8,40 0.8,52 49.6,52 49.6,0.8 ; 17 cut-outs
GND on BOTTOM: 0.8,0.8 0.8,9.5 11.5,9.5 11.5,40 0.8,40 0.8,52 49.6,52 49.6,0.8 ; 5 cut-outs
N05814 on TOP (solid shape): 39.1,23.7 34.75,23.7 34.75,25.25 39.1,25.25
N05832 on TOP (solid shape): 40,23.7 39.5,23.7 39.5,25.7 34.75,25.7 34.75,28.05 40,28.05
N05850 on TOP (solid shape): 44.75,23.7 40.4,23.7 40.4,28.05 44.75,28.05
N06055 on TOP (solid shape): 44.75,17.95 40.4,17.95 40.4,22.3 44.75,22.3
N06079 on TOP (solid shape): 40,17.95 39.5,17.95 39.5,22.3 40,22.3
N06104 on TOP (solid shape): 39.1,17.95 34.75,17.95 34.75,22.3 39.1,22.3

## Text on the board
Package Geometry/Pastemask Bottom: PASTEMASK BOT
Ref Des/Silkscreen Bottom: T9 | T2 | T3 | T12 | T13 | T6 | T7 | T4 | T5 | T8 | T10 | T11 | T14 | T15 | T16 | J1 | J2
Ref Des/Silkscreen Top: DMIC_0 | DMIC_1 | OM15081-2 | PCB2460-2 | JN5189 | RESET
PAGE_OUTLINE: TITRE | TITLE | . | No EVOL | DESSINE/DRAWN | ASCO-SR | REV. | Nbr/Qty | DATE | 29/01/2019 | EVOLUTION/CHANGE | M.BAUDRY | VERIFIE/CHECKED | NUMERO DOCUMENT/DOCUMENT NUMBER | DESS./DRAWN | APPROUVE/APPROVED | ..-..-.... | VERIF./CHECKED | PAGE | BP 2000 - COLOMBELLES | 14906 CAEN CEDEX 9 | 2 Esplanade Anton Philips | SEMICONDUCTORS | JN5189 AUDIO/LIGHT/SENSORS EXPANSION BOARD | / | PCB2460-2 | 00
DISPLAY_TOP: 1 | 2 | TOP LAYER | 311
USER_PART_NUM_TOP: 2 | BOTTOM LAYER | 311
TOLERANCE_TOP: 2 | 4 | LAYER 2 | 311
COMPVAL_TYPE_TOP: 3 | 4 | LAYER 3 | 311
User.18: 1 | SILKSCREEN TOP | 380
User.19: 2 | SOLDERMASK BOT | 312
User.20: 2 | PASTEMASK BOT | 435
User.22: 1 | 2 | PASTEMASK TOP | 435
User.24: 1 | 2 | SOLDERMASK TOP | 312
User.25: 1 | MILLING | 313
User.45: FIGURE | DIAMETRE / HOLESIZE | 0,30 mm (PERCE) | 0,80 mm +0,10 -0,05 | 0,90 mm +0,10 -0,05 | 1,10 mm +0,10 -0,05 | 0,35 mm +0,05 -0,05 | LEGENDE DE PERCAGE / DRILL LEGEND | ALL UNITS ARE IN MILLIMETERS | PLATED | NON-PLATED | Qte / Qty | 331 | 6 | 48 | 38 | 2 | <VIA | . | 17.5um | COLOR | BLUE | File. | 2/1 | 1/1 | 1 | JN5189 AUDIO/LIGHT/SENSORS EXPANSION BOARD | ASSEMBLY DRAWING TOP/BOTTOM OM15081-2 | PCB2460-2-400 | A
